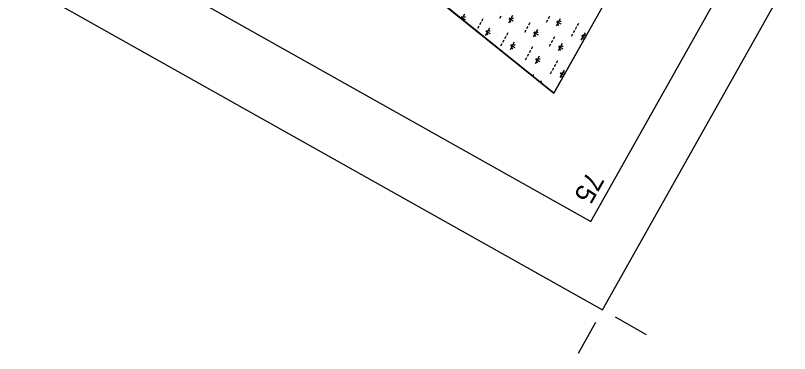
# Model space of a CAD drawing. Extents: x 3913936 to 3933962, y 195330 to 217741.
# Drawn here: x 3921301 to 3925814, y 195330 to 197302 of the extents above; entities that cross this region are included whole.
import ezdxf

# ---------------------------------------------------------------- set-up
doc = ezdxf.new("R2010")
doc.units = 0
for name, color, linetype in [('G-ANNO-NPLT', 7, 'Continuous'), ('V-ANNO-DIMS', 7, 'Continuous'), ('V-ANNO-SYMB', 7, 'Continuous'), ('V-ANNO-TEXT', 7, 'Continuous'), ('V-GRID-FRAM', 7, 'Continuous'), ('V-WETL-SWMP', 7, 'Continuous')]:
    doc.layers.add(name, color=color, linetype=linetype)

msp = doc.modelspace()

# ---------------------------------------------------------------- linework, layer by layer
at = {"layer": 'G-ANNO-NPLT'}
msp.add_lwpolyline([(3923174.4, 217486.3), (3914190.7, 201505), (3924723.8, 195583.9), (3933707.6, 211565.2)], close=True, dxfattribs=at)
at = {"layer": 'V-ANNO-DIMS'}
for p, q in [((3924796.5, 195543.1), (3924978.1, 195441)), ((3924683, 195511.2), (3924580.9, 195329.6))]:
    msp.add_line(p, q, dxfattribs=at)
at = {"layer": 'V-ANNO-SYMB'}
msp.add_lwpolyline([(3922773, 216134.5), (3914667.3, 201715.1), (3924655.6, 196100.2), (3932761.3, 210519.7), (3922773, 216134.5)], dxfattribs=at)
at = {"layer": 'V-GRID-FRAM'}
msp.add_lwpolyline([(3932010.3, 210315), (3924440.1, 196848.2), (3917917.6, 202110.6), (3924798.7, 214359), (3932010.3, 210315)], dxfattribs=at)
at = {"layer": 'V-WETL-SWMP'}
for p, q in [((3922914.5, 198079), (3924440.1, 196848.2)), ((3924440.1, 196848.2), (3924757.9, 197413.5)), ((3923919.4, 197309), (3923903.7, 197281)), ((3924130.9, 197298.4), (3924123.1, 197284.4)), ((3924199, 197301.7), (3924174.5, 197258.1)), ((3923903.4, 197296.2), (3923897.6, 197285.9)), ((3923907.2, 197287.2), (3923922.8, 197278.3)), ((3924014.2, 197260.7), (3924006.4, 197246.8)), ((3924026, 197281.6), (3924018.2, 197267.7)), ((3924183, 197288.9), (3924177.1, 197278.5)), ((3924186.8, 197279.9), (3924202.4, 197271.1)), ((3924299.4, 197258.7), (3924291.6, 197244.8)), ((3924403.7, 197274.6), (3924395.8, 197260.7)), ((3924415.4, 197295.5), (3924407.6, 197281.6)), ((3924477.4, 197283.2), (3924452.9, 197239.6)), ((3924461.3, 197270.4), (3924455.5, 197259.9)), ((3924465.1, 197261.4), (3924480.8, 197252.6)), ((3924584, 197255.9), (3924576.1, 197241.9)), ((3923990.7, 197218.9), (3923987.6, 197213.3)), ((3924002.5, 197239.8), (3923994.6, 197225.8)), ((3924064.4, 197227.4), (3924039.9, 197183.9)), ((3924048.4, 197214.7), (3924042.5, 197204.2)), ((3924275.9, 197216.9), (3924268.1, 197202.9)), ((3924287.7, 197237.8), (3924279.8, 197223.8)), ((3924344, 197220.2), (3924319.5, 197176.6)), ((3924560.4, 197214), (3924552.6, 197200.1)), ((3924572.2, 197234.9), (3924564.4, 197221)), ((3924052.2, 197205.6), (3924067.8, 197196.8)), ((3924159.2, 197179.2), (3924151.4, 197165.3)), ((3924171, 197200.1), (3924163.2, 197186.2)), ((3924328, 197207.4), (3924322.1, 197197)), ((3924331.8, 197198.4), (3924347.4, 197189.6)), ((3924444.4, 197177.2), (3924436.6, 197163.3)), ((3924548.7, 197193.1), (3924540.8, 197179.2)), ((3924622.4, 197201.7), (3924597.9, 197158.1)), ((3924606.3, 197188.9), (3924600.5, 197178.4)), ((3924610.1, 197179.9), (3924622.6, 197172.9)), ((3924135.7, 197137.4), (3924127.9, 197123.4)), ((3924147.5, 197158.3), (3924139.6, 197144.3)), ((3924209.4, 197145.9), (3924184.9, 197102.3)), ((3924193.4, 197133.2), (3924187.5, 197122.7)), ((3924197.2, 197124.1), (3924212.8, 197115.3)), ((3924316, 197118.6), (3924308.2, 197104.7)), ((3924420.9, 197135.4), (3924413.1, 197121.4)), ((3924432.7, 197156.3), (3924424.8, 197142.3)), ((3924489, 197138.7), (3924464.5, 197095.1)), ((3924473, 197125.9), (3924467.1, 197115.5)), ((3924292.5, 197076.8), (3924284.6, 197062.8)), ((3924304.2, 197097.7), (3924296.4, 197083.7)), ((3924476.8, 197116.9), (3924492.4, 197108.1)), ((3924280.7, 197055.9), (3924272.9, 197041.9)), ((3924354.4, 197064.4), (3924329.9, 197020.8)), ((3924338.4, 197051.6), (3924332.5, 197041.2)), ((3924342.1, 197042.6), (3924357.8, 197033.8)), ((3924461, 197037.1), (3924453.2, 197023.2)), ((3924437.5, 196995.3), (3924429.6, 196981.3)), ((3924449.2, 197016.2), (3924441.4, 197002.2)), ((3924499.4, 196982.9), (3924474.9, 196939.3)), ((3924321.5, 196958.4), (3924315.9, 196948.5)), ((3924425.7, 196974.3), (3924417.9, 196960.4)), ((3924483.4, 196970.1), (3924477.5, 196959.7)), ((3924487.1, 196961.1), (3924499.6, 196954.1)), ((3924366, 196920), (3924361.4, 196911.7))]:
    msp.add_line(p, q, dxfattribs=at)
for centre, start, end in [((3923920.9, 197311.1), 239.8861, 281.4297), ((3924173.4, 197255.7), 19.8861, 61.4297), ((3924200.5, 197303.9), 239.8861, 281.4297), ((3924478.9, 197285.4), 239.8861, 281.4297), ((3924065.9, 197229.6), 239.8861, 281.4297), ((3924451.8, 197237.2), 19.8861, 61.4297), ((3924038.8, 197181.5), 19.8861, 61.4297), ((3924318.4, 197174.2), 19.8861, 61.4297), ((3924345.5, 197222.4), 239.8861, 281.4297), ((3924596.8, 197155.7), 19.8861, 61.4297), ((3924623.9, 197203.8), 239.8861, 281.4297), ((3924210.9, 197148.1), 239.8861, 281.4297), ((3924490.5, 197140.9), 239.8861, 281.4297), ((3924183.8, 197099.9), 19.8861, 61.4297), ((3924463.4, 197092.7), 19.8861, 61.4297), ((3924328.8, 197018.4), 19.8861, 61.4297), ((3924355.9, 197066.6), 239.8861, 281.4297), ((3924473.8, 196936.9), 19.8861, 61.4297), ((3924500.9, 196985.1), 239.8861, 281.4297), ((3924367.5, 196922.1), 278.5301, 281.4297)]:
    msp.add_arc(centre, 17.6, start, end, dxfattribs=at)

# ---------------------------------------------------------------- texts
at = {"layer": 'V-ANNO-TEXT'}
msp.add_text('75', height=115, rotation=240.6579, dxfattribs=at).set_placement((3924638, 196398.9))

doc.saveas('drawing.dxf')
